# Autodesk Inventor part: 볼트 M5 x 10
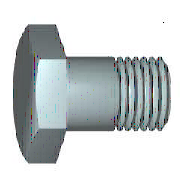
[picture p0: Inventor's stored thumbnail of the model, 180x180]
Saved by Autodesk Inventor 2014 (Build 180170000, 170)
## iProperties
IsCustomPart: 1
Created: 2012-02
Part Number: 볼트 M5 x 10
Material: 강철, 연강
Description: 6각 머리 볼트 및 6각 머리 나사
Document SubType Name: Modeling
Standard: KS B 1002
Designer: mduedu
Standards Organization: KS
Language: ko-KR
Size Designation: C  M 5 x 10
Categories: <MemberInstance><Categories><Category DisplayName="조임쇠" InternalName="e4da775c-781d-43d5-af7c-5136215cf5a6" Mnemonic="FSTN"><Category DisplayName="볼트" InternalN
Density: 1 g/cm^3
Appearance: 강철
Author: mduedu
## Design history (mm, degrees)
sketch "스케치1"
  geometry: L1 (0, 2.5)-(10, 2.5); L2 (10, 2.5)-(10, 0); L3 (10, 0)-(0, 0); L4 (-2, 0)-(12, 0) reference; L5 (0, -0.5)-(0, 3) reference; L6 (0, 2.5)-(0, 0)
  constraints: 8 end point, 3 point on line, 1 collinear
  dimensions: "d2" = 5 diameter of L1 L3 (= GD); "d59" = 10 distance between parallel lines of L2 L5 (= NLG)
revolve "본체" sketch "스케치1" stored, may be unused: angle "d12" = 90 deg
sketch "스케치2"
  geometry: L1 (0, 4.619)-(4, 2.309); L2 (4, 2.309)-(4, -2.309); L3 (4, -2.309)-(0, -4.619); L4 (0, -4.619)-(-4, -2.309); L5 (-4, -2.309)-(-4, 2.309); L6 (-4, 2.309)-(0, 4.619); L7 (-5.6, 0)-(5.6, 0) reference; L8 (0, 6.466)-(0, -6.466) reference; 2 further points
  constraints: 12 end point, 2 midpoint, 1 coincident, 1 vertical, 11 other
  dimensions: "d11" = 8 distance between parallel lines of L5 L2 (= SW)
extrude "머리" join sketch "스케치2" distance "d3" = 3.5 (= KOH); taper "d4" = 0 deg
revolve "모따기1" stored, may be unused: angle "d21" = 90 deg
workplane "Work Plane1"
body "Solid1"
feature "스레드" dims "d15" = 7.6 (= GEL), "d16" = 0
chamfer "모따기2" distance "d6" = 0.49076 (= -0.5 x SPD + 0.5 x GD); stored, may be unused: second distance "d7" = 0.49086 (computed from GUL), angle "d55" = 45 deg
sketch "스케치4"
  geometry: L1 (-3.038, 4.8)-(-3.5, 4); L2 (-1.1, 0)-(-0.234, 0); L3 (-4.153, 0)-(0.419, 0) reference; L4 (-3.5, 4.8)-(-3.038, 4.8); L5 (-3.5, 4)-(-3.5, 4.8); L6 (0, 5.76)-(0, -0.96) reference
  constraints: 8 end point, 1 parallel, 1 perpendicular, 1 point on line
  dimensions: "d65" = 8 diameter of L1.end L2 (= SW); "d67" = 30 deg angle of L1 L5 (= ANG1); "d68" = 9.6 diameter of L4 L2 (= 1.2 x SW); "d69" = 3.5 distance between parallel lines of L5 L6 (= KOH)
other parameters: "NLG" = 10 [user parameter; used in 1 equation term], "GD" = 5 (= NND) [user parameter; used in 2 equation terms], "BDM" = 5 (= NND) [user parameter], "KOH" = 3.5 [user parameter; used in 2 equation terms], "GEL" = 7.6 [user parameter; used in 1 equation term], "SW" = 8 [user parameter; used in 5 equation terms], "SW0" = 8 (= SW) [user parameter], "SPD" = 4.01848 (= NND - 1.2269 x PTC) [user parameter; used in 1 equation term], "SD2" = 5 (= NND) [user parameter], "SD" = 0 [user parameter], "ANG1" = 30 deg [user parameter; used in 1 equation term], "GAL" = 0.49076 (= 0.61345 x PTC) [user parameter], "GUL" = 0.49076 (= 0.61345 x PTC) [user parameter; used in 1 equation term], "d8" = 0, "RR" = 0.2 [user parameter], "d58" = 0, "RR1" = 0.1 [user parameter], "TPU" = 12.5 (computed from PTC) [user parameter], "GD1" = 4.01848 (= THREADDIA - 1.2269 x PTC) [user parameter], "THREADDIA" = 5 [user parameter; used in 1 equation term], "TOA" = 30 deg [user parameter], "PTC" = 0.8 [user parameter; used in 5 equation terms], "NND" = 5 [user parameter; used in 4 equation terms], "E0" = 9.24 (= 1.155 x SW) [user parameter]
